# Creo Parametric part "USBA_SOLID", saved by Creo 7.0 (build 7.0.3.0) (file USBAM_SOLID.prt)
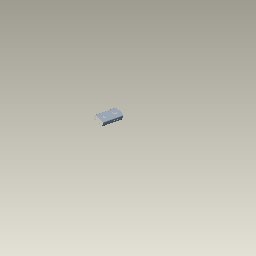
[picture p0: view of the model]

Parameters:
  PTC_COMMON_NAME = "usba_solid.prt"
  PTC_WM_REVISION = "A"
  PTC_WM_ITERATION = "1"
  PTC_WM_VERSION = "A.1"
  PTC_WM_LIFECYCLE_STATE = "Concept"
  PTC_WM_LIFECYCLE = "Life Cycle Schema Type 1"
  PTC_WM_CREATED_BY = "Mike Minsterketter"
  PTC_WM_CREATED_ON = "2022-02-24"
  PTC_WM_MODIFIED_BY = "Mike Minsterketter"
  PTC_WM_MODIFIED_ON = "2022-03-07"
  PDMREV = "A.1+"
  PDMRL = "Concept"
  PROI_REVISION = "A"
  PROI_VERSION = "1+"
  PROI_RELEASE = "Concept"
  COPY_GEOM_ORIGIN_TYPE = "Part"

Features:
  1. datum plane "RIGHT"
  2. datum plane "TOP"
  3. datum plane "FRONT"
  4. coordinate system
  5. datum axis
  6. datum axis
  7. datum axis
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
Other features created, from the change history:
  patch "Solidify 4"
  planar section "A"
  extrusion "Extrude 1"
  mirror "Mirror 3"
  extrusion "Extrude 1 (2)"
  curve "Copy 1"
  feature "Copy 1" (2 times)
  feature "Extend 1" (2 times)
  feature "Extend 2" (2 times)
  feature "Extrude 2"
  patch "Solidify 5"
  feature "Copy 2"
  patch "Solidify 6"
  planar section "B"
  extrusion "Extrude 2"
  feature "Copy 3"
  feature "Extend 3"
  fill "Fill 8"
  feature "Merge 10"
  patch "Solidify 7"
  feature "Copy 4"
  feature "Extend 4"
  fill "Fill 9"
  feature "Merge 11" (2 times)
  feature "Offset Geometry 1"
  coordinate system "CS1"
  coordinate system "CS2"
  imported feature "Import Feature id 11292"
  imported feature "Import Feature id 21227"
  imported feature "Import Feature id 28479"

Other named items: X-AXES, Y-AXES, Z-AXES, CS0

Layers: .WHITE_HOLE, ANNOTATIONS, AXES, COSMETICS, CSYS, CURVES, EXT_COPY_GEOM, PLANES, POINTS, PUBLISHED_GEOM, QUILTS, SOLIDS, STARTUP

Notes: NOT SPECIFIED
